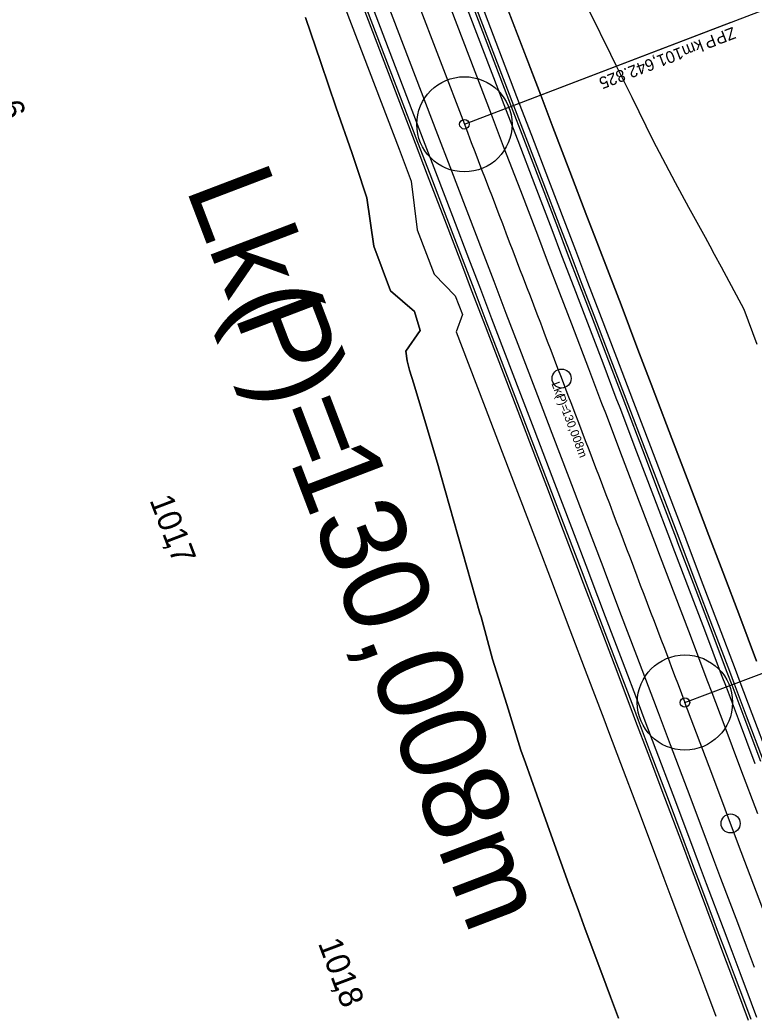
# Model space of a CAD drawing. Extents: x -678487 to -674601, y -1104811 to -1093295.
# Drawn here: x -676866.3 to -676712.1, y -1098531.5 to -1098322.4 of the extents above; entities that cross this region are included whole.
import ezdxf

# ---------------------------------------------------------------- set-up
doc = ezdxf.new("R2010")
doc.units = 0
for name, color, linetype in [('SOxxxxxx_Koleje_dopravna_Popis', 7, 'Continuous'), ('SOxxxxxx_Koleje_hlavní_body_Popis', 7, 'Continuous'), ('SOxxxxxx_Koleje_hlavní_body_Popis10', 7, 'Continuous'), ('SOxxxxxx_Koleje_param další_Popis', 7, 'Continuous'), ('SOxxxxxx_Koleje_param další_Popis10', 7, 'Continuous'), ('SOxxxxxx_Osa_bod_P', 7, 'Continuous'), ('SOxxxxxx_Staničení_Popis', 7, 'Continuous'), ('SOxxxxxx_ŽSp_hrana', 7, 'Continuous'), ('SOxxxxxx_ŽSp_odvodnění', 7, 'Continuous'), ('SOxxxxxx_ŽSp_zářez_hrana', 7, 'Continuous'), ('SOxxxxxx_ŽSp_zářez_plocha', 7, 'Continuous')]:
    doc.layers.add(name, color=color, linetype=linetype)

msp = doc.modelspace()

# ---------------------------------------------------------------- linework, layer by layer
at = {"layer": 'SOxxxxxx_Koleje_hlavní_body_Popis'}
for p, q in [((-676772.96, -1098344.36), (-676716.93, -1098322.92)), ((-676772.96, -1098344.36), (-676772.96, -1098344.36)), ((-676726.65, -1098465.84), (-676670.54, -1098444.6)), ((-676726.65, -1098465.84), (-676726.65, -1098465.84))]:
    msp.add_line(p, q, dxfattribs=at)
for centre in [(-676772.96, -1098344.36), (-676726.65, -1098465.84)]:
    msp.add_circle(centre, 1, dxfattribs=at)
at = {"layer": 'SOxxxxxx_Koleje_hlavní_body_Popis10'}
for p, q in [((-676772.96, -1098344.36), (-676212.59, -1098129.94)), ((-676726.65, -1098465.84), (-676165.5, -1098253.44)), ((-676772.96, -1098344.36), (-676772.96, -1098344.36)), ((-676726.65, -1098465.84), (-676726.65, -1098465.84))]:
    msp.add_line(p, q, dxfattribs=at)
for centre in [(-676772.96, -1098344.36), (-676726.65, -1098465.84)]:
    msp.add_circle(centre, 10, dxfattribs=at)
at = {"layer": 'SOxxxxxx_Osa_bod_P'}
msp.add_line((-676865.88, -1098101.53), (-676772.96, -1098344.36), dxfattribs=at)
msp.add_arc((-693563.22, -1104838.51), 18002.25, 14.227837, 20.731742, dxfattribs=at)
msp.add_open_spline([(-676772.96, -1098344.36), (-676769.09, -1098354.48), (-676761.35, -1098374.72), (-676749.75, -1098405.08), (-676738.17, -1098435.45), (-676730.49, -1098455.71), (-676726.65, -1098465.84)], degree=3, dxfattribs=at)
at = {"layer": 'SOxxxxxx_Staničení_Popis'}
for p, q in [((-676752.54, -1098397.77), (-676752.54, -1098397.77)), ((-676717.05, -1098491.25), (-676717.05, -1098491.25))]:
    msp.add_line(p, q, dxfattribs=at)
for centre in [(-676752.54, -1098397.77), (-676717.05, -1098491.25)]:
    msp.add_circle(centre, 2, dxfattribs=at)
at = {"layer": 'SOxxxxxx_ŽSp_hrana'}
for points in [[(-676818.39, -1098208.83), (-676767.35, -1098342.22), (-676764.78, -1098348.92), (-676761.21, -1098358.26), (-676757.64, -1098367.6), (-676755.56, -1098373.05), (-676752.99, -1098379.75), (-676750.5, -1098386.29), (-676746.93, -1098395.63), (-676744.14, -1098402.94), (-676743.36, -1098404.97), (-676739.8, -1098414.32), (-676736.24, -1098423.66), (-676732.68, -1098433.01), (-676732.38, -1098433.79), (-676729.13, -1098442.36), (-676725.58, -1098451.71), (-676722.03, -1098461.06), (-676721.03, -1098463.71), (-676718.49, -1098470.42), (-676714.96, -1098479.78), (-676711.43, -1098489.14)], [(-676829.62, -1098213.11), (-676778.58, -1098346.5), (-676776.02, -1098353.2), (-676772.44, -1098362.54), (-676768.87, -1098371.88), (-676766.79, -1098377.32), (-676764.23, -1098384.02), (-676761.73, -1098390.56), (-676758.16, -1098399.9), (-676755.37, -1098407.22), (-676754.6, -1098409.24), (-676751.03, -1098418.59), (-676747.47, -1098427.93), (-676743.92, -1098437.28), (-676743.62, -1098438.05), (-676740.37, -1098446.62), (-676736.82, -1098455.97), (-676733.27, -1098465.32), (-676732.27, -1098467.97), (-676729.74, -1098474.67), (-676726.2, -1098484.02), (-676722.68, -1098493.37), (-676720.62, -1098498.83), (-676719.15, -1098502.73), (-676715.64, -1098512.09), (-676713.8, -1098516.98), (-676712.13, -1098521.45)]]:
    msp.add_lwpolyline(points, dxfattribs=at)
at = {"layer": 'SOxxxxxx_ŽSp_odvodnění'}
for p, q in [((-676823.62, -1098242.92), (-676783.3, -1098348.29)), ((-676823.11, -1098242.72), (-676782.79, -1098348.1)), ((-676799.89, -1098244.59), (-676763.14, -1098340.62)), ((-676799.37, -1098244.39), (-676762.63, -1098340.43)), ((-676763.14, -1098340.62), (-676760.58, -1098347.32)), ((-676762.63, -1098340.43), (-676760.06, -1098347.13)), ((-676782.79, -1098348.1), (-676780.22, -1098354.8)), ((-676760.58, -1098347.32), (-676757, -1098356.66)), ((-676760.06, -1098347.13), (-676756.49, -1098356.47)), ((-676783.3, -1098348.29), (-676780.74, -1098355)), ((-676780.74, -1098355), (-676777.16, -1098364.34)), ((-676780.22, -1098354.8), (-676776.65, -1098364.14)), ((-676756.49, -1098356.47), (-676752.92, -1098365.81)), ((-676757, -1098356.66), (-676753.43, -1098366)), ((-676777.16, -1098364.34), (-676773.59, -1098373.68)), ((-676776.65, -1098364.14), (-676773.08, -1098373.48)), ((-676753.43, -1098366), (-676751.35, -1098371.45)), ((-676752.92, -1098365.81), (-676750.84, -1098371.25)), ((-676751.35, -1098371.45), (-676748.79, -1098378.15)), ((-676750.84, -1098371.25), (-676748.27, -1098377.95)), ((-676773.59, -1098373.68), (-676771.51, -1098379.12)), ((-676773.08, -1098373.48), (-676771, -1098378.92)), ((-676771.51, -1098379.12), (-676768.95, -1098385.82)), ((-676771, -1098378.92), (-676768.43, -1098385.62)), ((-676748.79, -1098378.15), (-676746.29, -1098384.69)), ((-676748.27, -1098377.95), (-676745.78, -1098384.49)), ((-676768.43, -1098385.62), (-676765.94, -1098392.16)), ((-676746.29, -1098384.69), (-676742.72, -1098394.03)), ((-676745.78, -1098384.49), (-676742.21, -1098393.83)), ((-676768.95, -1098385.82), (-676766.45, -1098392.36)), ((-676766.45, -1098392.36), (-676762.88, -1098401.7)), ((-676765.94, -1098392.16), (-676762.37, -1098401.5)), ((-676742.72, -1098394.03), (-676739.93, -1098401.34)), ((-676742.21, -1098393.83), (-676739.42, -1098401.15)), ((-676762.88, -1098401.7), (-676760.09, -1098409.01)), ((-676762.37, -1098401.5), (-676759.58, -1098408.82)), ((-676739.93, -1098401.34), (-676739.16, -1098403.37)), ((-676739.42, -1098401.15), (-676738.64, -1098403.18)), ((-676739.16, -1098403.37), (-676735.59, -1098412.72)), ((-676738.64, -1098403.18), (-676735.08, -1098412.52)), ((-676760.09, -1098409.01), (-676759.32, -1098411.04)), ((-676759.58, -1098408.82), (-676758.8, -1098410.84)), ((-676758.8, -1098410.84), (-676755.24, -1098420.19)), ((-676759.32, -1098411.04), (-676755.75, -1098420.38)), ((-676735.59, -1098412.72), (-676732.03, -1098422.06)), ((-676735.08, -1098412.52), (-676731.52, -1098421.87)), ((-676755.75, -1098420.38), (-676752.19, -1098429.72)), ((-676755.24, -1098420.19), (-676751.68, -1098429.53)), ((-676732.03, -1098422.06), (-676728.47, -1098431.41)), ((-676731.52, -1098421.87), (-676727.96, -1098431.22)), ((-676751.68, -1098429.53), (-676748.12, -1098438.87)), ((-676752.19, -1098429.72), (-676748.64, -1098439.07)), ((-676728.47, -1098431.41), (-676728.18, -1098432.19)), ((-676727.96, -1098431.22), (-676727.66, -1098432)), ((-676728.18, -1098432.19), (-676724.92, -1098440.76)), ((-676727.66, -1098432), (-676724.4, -1098440.57)), ((-676748.64, -1098439.07), (-676748.34, -1098439.84)), ((-676748.34, -1098439.84), (-676745.09, -1098448.41)), ((-676748.12, -1098438.87), (-676747.83, -1098439.65)), ((-676747.83, -1098439.65), (-676744.57, -1098448.22)), ((-676724.92, -1098440.76), (-676721.37, -1098450.12)), ((-676724.4, -1098440.57), (-676720.85, -1098449.92)), ((-676745.09, -1098448.41), (-676741.54, -1098457.76)), ((-676744.57, -1098448.22), (-676741.03, -1098457.56)), ((-676721.37, -1098450.12), (-676717.82, -1098459.47)), ((-676720.85, -1098449.92), (-676717.31, -1098459.28)), ((-676741.54, -1098457.76), (-676738, -1098467.1)), ((-676741.03, -1098457.56), (-676737.48, -1098466.91)), ((-676717.82, -1098459.47), (-676716.82, -1098462.12)), ((-676717.31, -1098459.28), (-676716.31, -1098461.93)), ((-676716.82, -1098462.12), (-676714.28, -1098468.83)), ((-676716.31, -1098461.93), (-676713.77, -1098468.63)), ((-676738, -1098467.1), (-676737, -1098469.75)), ((-676737.48, -1098466.91), (-676736.48, -1098469.56)), ((-676714.28, -1098468.83), (-676710.75, -1098478.19)), ((-676713.77, -1098468.63), (-676710.23, -1098477.99)), ((-676737, -1098469.75), (-676734.46, -1098476.45)), ((-676736.48, -1098469.56), (-676733.95, -1098476.26)), ((-676734.46, -1098476.45), (-676730.93, -1098485.8)), ((-676733.95, -1098476.26), (-676730.41, -1098485.61)), ((-676730.93, -1098485.8), (-676727.4, -1098495.15)), ((-676730.41, -1098485.61), (-676726.89, -1098494.96)), ((-676727.4, -1098495.15), (-676725.35, -1098500.61)), ((-676726.89, -1098494.96), (-676724.83, -1098500.42)), ((-676725.35, -1098500.61), (-676723.88, -1098504.51)), ((-676724.83, -1098500.42), (-676723.37, -1098504.31)), ((-676723.88, -1098504.51), (-676720.37, -1098513.86)), ((-676723.37, -1098504.31), (-676719.85, -1098513.67)), ((-676720.37, -1098513.86), (-676718.53, -1098518.76)), ((-676719.85, -1098513.67), (-676718.01, -1098518.56)), ((-676718.53, -1098518.76), (-676716.85, -1098523.22)), ((-676718.01, -1098518.56), (-676716.34, -1098523.03)), ((-676716.85, -1098523.22), (-676714.48, -1098529.57)), ((-676716.34, -1098523.03), (-676713.96, -1098529.38)), ((-676714.48, -1098529.57), (-676713.35, -1098532.58)), ((-676713.96, -1098529.38), (-676712.83, -1098532.39))]:
    msp.add_line(p, q, dxfattribs=at)
at = {"layer": 'SOxxxxxx_ŽSp_zářez_hrana'}
for p, q in [((-676825.49, -1098232.93), (-676781.59, -1098347.64)), ((-676804.66, -1098235.7), (-676764.34, -1098341.08)), ((-676798.18, -1098243.94), (-676761.43, -1098339.97)), ((-676772.23, -1098298.26), (-676756.93, -1098338.26)), ((-676746.69, -1098320.64), (-676742.28, -1098329.66)), ((-676806.33, -1098321.94), (-676803.08, -1098331.4)), ((-676803.08, -1098331.4), (-676799.85, -1098340.87)), ((-676742.28, -1098329.66), (-676741.01, -1098332.2)), ((-676741.01, -1098332.2), (-676737.82, -1098338.66)), ((-676756.93, -1098338.26), (-676754.36, -1098344.96)), ((-676737.82, -1098338.66), (-676733.37, -1098347.67)), ((-676799.85, -1098340.87), (-676796.58, -1098350.32)), ((-676764.34, -1098341.08), (-676761.77, -1098347.78)), ((-676761.43, -1098339.97), (-676758.87, -1098346.67)), ((-676754.36, -1098344.96), (-676750.79, -1098354.3)), ((-676781.59, -1098347.64), (-676779.03, -1098354.35)), ((-676761.77, -1098347.78), (-676758.2, -1098357.12)), ((-676758.87, -1098346.67), (-676755.29, -1098356.01)), ((-676733.37, -1098347.67), (-676728.71, -1098356.6)), ((-676796.58, -1098350.32), (-676795.68, -1098353)), ((-676795.68, -1098353), (-676793.44, -1098359.83)), ((-676779.03, -1098354.35), (-676775.45, -1098363.68)), ((-676750.79, -1098354.3), (-676747.22, -1098363.64)), ((-676755.29, -1098356.01), (-676751.72, -1098365.35)), ((-676758.2, -1098357.12), (-676754.63, -1098366.46)), ((-676728.71, -1098356.6), (-676725.87, -1098361.75)), ((-676793.44, -1098359.83), (-676791.95, -1098369.96)), ((-676725.87, -1098361.75), (-676722.39, -1098368.1)), ((-676775.45, -1098363.68), (-676771.88, -1098373.02)), ((-676747.22, -1098363.64), (-676745.14, -1098369.08)), ((-676754.63, -1098366.46), (-676752.55, -1098371.9)), ((-676751.72, -1098365.35), (-676749.64, -1098370.8)), ((-676722.39, -1098368.1), (-676721.43, -1098369.87)), ((-676791.95, -1098369.96), (-676788.49, -1098379.34)), ((-676749.64, -1098370.8), (-676747.08, -1098377.5)), ((-676745.14, -1098369.08), (-676742.57, -1098375.78)), ((-676721.43, -1098369.87), (-676720.48, -1098371.65)), ((-676771.88, -1098373.02), (-676769.8, -1098378.47)), ((-676752.55, -1098371.9), (-676749.99, -1098378.6)), ((-676720.48, -1098371.65), (-676719.04, -1098374.32)), ((-676719.04, -1098374.32), (-676714.27, -1098383.2)), ((-676742.57, -1098375.78), (-676740.07, -1098382.32)), ((-676788.49, -1098379.34), (-676783.46, -1098383.66)), ((-676769.8, -1098378.47), (-676767.24, -1098385.17)), ((-676749.99, -1098378.6), (-676747.49, -1098385.14)), ((-676747.08, -1098377.5), (-676744.58, -1098384.04)), ((-676783.46, -1098383.66), (-676782.23, -1098387.66)), ((-676740.07, -1098382.32), (-676736.51, -1098391.66)), ((-676714.27, -1098383.2), (-676711.52, -1098390.54)), ((-676767.24, -1098385.17), (-676764.74, -1098391.71)), ((-676747.49, -1098385.14), (-676743.92, -1098394.48)), ((-676744.58, -1098384.04), (-676741.01, -1098393.38)), ((-676782.23, -1098387.66), (-676785.26, -1098392.02)), ((-676785.26, -1098392.02), (-676784.98, -1098394.06)), ((-676764.74, -1098391.71), (-676761.17, -1098401.05)), ((-676736.51, -1098391.66), (-676733.71, -1098398.98)), ((-676784.98, -1098394.06), (-676784.45, -1098396)), ((-676741.01, -1098393.38), (-676738.22, -1098400.69)), ((-676784.45, -1098396), (-676783.56, -1098398.87)), ((-676743.92, -1098394.48), (-676741.13, -1098401.8)), ((-676783.56, -1098398.87), (-676780.69, -1098408.47)), ((-676733.71, -1098398.98), (-676732.94, -1098401.01)), ((-676761.17, -1098401.05), (-676758.38, -1098408.36)), ((-676741.13, -1098401.8), (-676740.35, -1098403.83)), ((-676738.22, -1098400.69), (-676737.44, -1098402.72)), ((-676732.94, -1098401.01), (-676729.37, -1098410.36)), ((-676740.35, -1098403.83), (-676736.79, -1098413.17)), ((-676737.44, -1098402.72), (-676733.88, -1098412.07)), ((-676780.69, -1098408.47), (-676778.48, -1098416.01)), ((-676758.38, -1098408.36), (-676757.61, -1098410.39)), ((-676757.61, -1098410.39), (-676754.04, -1098419.73)), ((-676729.37, -1098410.36), (-676725.81, -1098419.7)), ((-676733.88, -1098412.07), (-676730.32, -1098421.41)), ((-676736.79, -1098413.17), (-676733.23, -1098422.52)), ((-676778.48, -1098416.01), (-676777.87, -1098418.1)), ((-676777.87, -1098418.1), (-676775.14, -1098427.75)), ((-676754.04, -1098419.73), (-676750.48, -1098429.07)), ((-676725.81, -1098419.7), (-676722.26, -1098429.05)), ((-676733.23, -1098422.52), (-676729.67, -1098431.87)), ((-676730.32, -1098421.41), (-676726.76, -1098430.76)), ((-676775.14, -1098427.75), (-676772.46, -1098437.42)), ((-676750.48, -1098429.07), (-676746.93, -1098438.42)), ((-676722.26, -1098429.05), (-676721.96, -1098429.83)), ((-676726.76, -1098430.76), (-676726.47, -1098431.54)), ((-676726.47, -1098431.54), (-676723.21, -1098440.11)), ((-676721.96, -1098429.83), (-676718.7, -1098438.41)), ((-676729.67, -1098431.87), (-676729.37, -1098432.65)), ((-676729.37, -1098432.65), (-676726.12, -1098441.22)), ((-676772.46, -1098437.42), (-676769.68, -1098447.05)), ((-676746.93, -1098438.42), (-676746.63, -1098439.19)), ((-676746.63, -1098439.19), (-676743.38, -1098447.76)), ((-676723.21, -1098440.11), (-676719.66, -1098449.47)), ((-676718.7, -1098438.41), (-676715.15, -1098447.76)), ((-676726.12, -1098441.22), (-676722.57, -1098450.57)), ((-676769.68, -1098447.05), (-676769.46, -1098447.86)), ((-676769.46, -1098447.86), (-676767.08, -1098456.75)), ((-676743.38, -1098447.76), (-676739.83, -1098457.11)), ((-676715.15, -1098447.76), (-676711.6, -1098457.12)), ((-676722.57, -1098450.57), (-676719.02, -1098459.92)), ((-676719.66, -1098449.47), (-676716.11, -1098458.82)), ((-676767.08, -1098456.75), (-676764.06, -1098466.29)), ((-676739.83, -1098457.11), (-676736.29, -1098466.46)), ((-676716.11, -1098458.82), (-676715.11, -1098461.47)), ((-676719.02, -1098459.92), (-676718.02, -1098462.57)), ((-676718.02, -1098462.57), (-676715.48, -1098469.28)), ((-676715.11, -1098461.47), (-676712.57, -1098468.18)), ((-676764.06, -1098466.29), (-676761.13, -1098475.86)), ((-676736.29, -1098466.46), (-676735.28, -1098469.11)), ((-676735.28, -1098469.11), (-676732.75, -1098475.81)), ((-676715.48, -1098469.28), (-676711.95, -1098478.64)), ((-676712.57, -1098468.18), (-676709.04, -1098477.54)), ((-676761.13, -1098475.86), (-676760.16, -1098478.51)), ((-676732.75, -1098475.81), (-676729.22, -1098485.16)), ((-676760.16, -1098478.51), (-676757.74, -1098485.25)), ((-676757.74, -1098485.25), (-676754.41, -1098494.66)), ((-676729.22, -1098485.16), (-676725.69, -1098494.51)), ((-676725.69, -1098494.51), (-676723.63, -1098499.97)), ((-676754.41, -1098494.66), (-676751, -1098504.05)), ((-676723.63, -1098499.97), (-676722.17, -1098503.86)), ((-676751, -1098504.05), (-676749.01, -1098509.52)), ((-676722.17, -1098503.86), (-676718.65, -1098513.22)), ((-676749.01, -1098509.52), (-676747.6, -1098513.43)), ((-676718.65, -1098513.22), (-676716.82, -1098518.11)), ((-676747.6, -1098513.43), (-676744.13, -1098522.79)), ((-676716.82, -1098518.11), (-676715.14, -1098522.58)), ((-676744.13, -1098522.79), (-676742.3, -1098527.67)), ((-676715.14, -1098522.58), (-676712.76, -1098528.93)), ((-676742.3, -1098527.67), (-676740.63, -1098532.13)), ((-676712.76, -1098528.93), (-676711.64, -1098531.94))]:
    msp.add_line(p, q, dxfattribs=at)
at = {"layer": 'SOxxxxxx_ŽSp_zářez_plocha'}
for points in [[(-676826.99, -1098244.2), (-676786.67, -1098349.58), (-676784.1, -1098356.28), (-676782.87, -1098366.51), (-676779.29, -1098375.85), (-676774.87, -1098380.4), (-676773.38, -1098384.3), (-676774.65, -1098387.99), (-676772.15, -1098394.53), (-676768.58, -1098403.87), (-676765.79, -1098411.18), (-676765.02, -1098413.21), (-676761.46, -1098422.55), (-676757.9, -1098431.89), (-676754.34, -1098441.23), (-676754.05, -1098442.01), (-676750.79, -1098450.57), (-676747.24, -1098459.92), (-676743.7, -1098469.26), (-676742.7, -1098471.91), (-676740.17, -1098478.61), (-676736.64, -1098487.96), (-676733.11, -1098497.31), (-676731.06, -1098502.76), (-676729.59, -1098506.66), (-676726.08, -1098516.01), (-676724.24, -1098520.9), (-676722.57, -1098525.36), (-676720.19, -1098531.71)], [(-676711.6, -1098457.12), (-676715.15, -1098447.76), (-676718.7, -1098438.41), (-676721.96, -1098429.83), (-676722.26, -1098429.05), (-676725.81, -1098419.7), (-676729.37, -1098410.36), (-676732.94, -1098401.01), (-676733.71, -1098398.98), (-676736.51, -1098391.66), (-676740.07, -1098382.32), (-676742.57, -1098375.78), (-676745.14, -1098369.08), (-676747.22, -1098363.64), (-676750.79, -1098354.3), (-676754.36, -1098344.96), (-676756.93, -1098338.26), (-676772.23, -1098298.26)], [(-676746.69, -1098320.64), (-676742.28, -1098329.66), (-676741.01, -1098332.2), (-676737.82, -1098338.66), (-676733.37, -1098347.67), (-676728.71, -1098356.6), (-676725.87, -1098361.75), (-676722.39, -1098368.1), (-676721.43, -1098369.87), (-676720.48, -1098371.65), (-676719.04, -1098374.32), (-676714.27, -1098383.2), (-676711.52, -1098390.54)], [(-676740.63, -1098532.13), (-676742.3, -1098527.67), (-676744.13, -1098522.79), (-676747.6, -1098513.43), (-676749.01, -1098509.52), (-676751, -1098504.05), (-676754.41, -1098494.66), (-676757.74, -1098485.25), (-676760.16, -1098478.51), (-676761.13, -1098475.86), (-676764.06, -1098466.29), (-676767.08, -1098456.75), (-676769.46, -1098447.86), (-676769.68, -1098447.05), (-676772.46, -1098437.42), (-676775.14, -1098427.75), (-676777.87, -1098418.1), (-676778.48, -1098416.01), (-676780.69, -1098408.47), (-676783.56, -1098398.87), (-676784.45, -1098396), (-676784.98, -1098394.06), (-676785.26, -1098392.02), (-676782.23, -1098387.66), (-676783.46, -1098383.66), (-676788.49, -1098379.34), (-676791.95, -1098369.96), (-676793.44, -1098359.83), (-676795.68, -1098353), (-676796.58, -1098350.32), (-676799.85, -1098340.87), (-676803.08, -1098331.4), (-676806.33, -1098321.94)]]:
    msp.add_lwpolyline(points, dxfattribs=at)

# ---------------------------------------------------------------- texts
at = {"layer": 'SOxxxxxx_Koleje_dopravna_Popis'}
msp.add_text('ŽST SVĚTLÁ NAD SÁZAVOU', height=50, rotation=318.3161, dxfattribs=at).set_placement((-677417.14, -1098450.27))
at = {"layer": 'SOxxxxxx_Koleje_hlavní_body_Popis'}
for s, p in [('ZP', (-676716.57, -1098323.85)), (' km ', (-676722.51, -1098326.13)), ('P', (-676720.73, -1098325.45)), ('101,642.825', (-676727.57, -1098328.06))]:
    msp.add_text(s, height=2.5, rotation=200.9386, dxfattribs=at).set_placement(p)
at = {"layer": 'SOxxxxxx_Koleje_param další_Popis'}
for s, p in [('Lk(', (-676754.7, -1098398.85)), (')=', (-676753.19, -1098402.81)), ('P', (-676753.68, -1098401.52)), ('130,008m', (-676752.51, -1098404.58))]:
    msp.add_text(s, height=1.8, rotation=290.8869, dxfattribs=at).set_placement(p)
at = {"layer": 'SOxxxxxx_Koleje_param další_Popis10'}
for s, p in [('Lk(', (-676831.57, -1098357.68)), ('P', (-676821.36, -1098384.44)), (')=', (-676816.46, -1098397.28)), ('130,008m', (-676809.71, -1098414.96))]:
    msp.add_text(s, height=18, rotation=290.8869, dxfattribs=at).set_placement(p)
at = {"layer": 'SOxxxxxx_Staničení_Popis'}
for s, rotation, p in [('6', 290.9386, (-676870.85, -1098340.38)), ('101', 290.8986, (-676839.13, -1098423.3)), (',', 290.8986, (-676835.72, -1098432.23)), ('7', 290.8986, (-676835.15, -1098433.72)), ('101', 290.6453, (-676803.75, -1098516.4)), (',', 290.6453, (-676800.39, -1098525.34)), ('8', 290.6453, (-676799.82, -1098526.84))]:
    msp.add_text(s, height=5, rotation=rotation, dxfattribs=at).set_placement(p)

doc.saveas('drawing.dxf')
